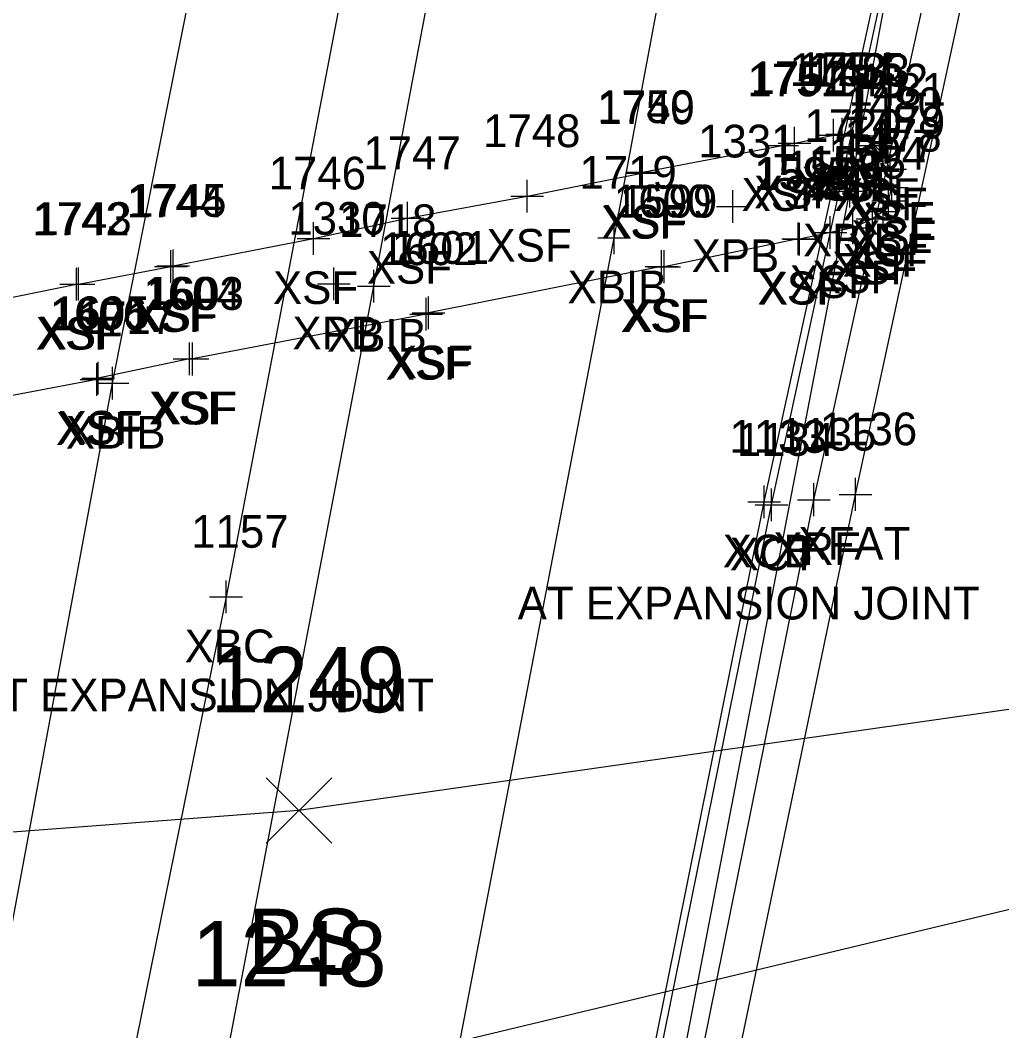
# Model space of a CAD drawing. Extents: x 1683147 to 1683637, y 416837 to 418211.
# Drawn here: x 1683250.16 to 1683280.15, y 417577.53 to 417608.4 of the extents above; entities that cross this region are included whole.
import ezdxf

# ---------------------------------------------------------------- set-up
doc = ezdxf.new("R2010")
doc.units = 0
for name, color, linetype in [('B_A', 7, 'Continuous'), ('B_C', 7, 'Continuous'), ('B_I', 7, 'Continuous'), ('B_TIC', 7, 'Continuous'), ('BB', 7, 'Continuous'), ('BDC', 7, 'Continuous'), ('BDEFAULT', 7, 'Continuous'), ('BELB', 7, 'Continuous'), ('BF', 7, 'Continuous'), ('BR', 7, 'Continuous'), ('L_A', 7, 'Continuous'), ('L_I', 7, 'Continuous'), ('L_TIC', 7, 'Continuous'), ('LELB', 7, 'Continuous')]:
    doc.layers.add(name, color=color, linetype=linetype)

msp = doc.modelspace()

# ---------------------------------------------------------------- linework, layer by layer
at = {"layer": 'B_TIC'}
for p, q in [((1683275.274, 417604.925), (1683275.35, 417604.925)), ((1683273.821, 417604.651), (1683273.897, 417604.651)), ((1683275.014, 417604.895), (1683275.09, 417604.895)), ((1683275.554, 417604.898), (1683275.63, 417604.898)), ((1683275.554, 417604.898), (1683275.63, 417604.898)), ((1683275.715, 417604.873), (1683275.79, 417604.873)), ((1683273.443, 417604.578), (1683273.518, 417604.578)), ((1683276.275, 417604.577), (1683276.35, 417604.577)), ((1683276.531, 417604.291), (1683276.606, 417604.291)), ((1683269.152, 417603.728), (1683269.227, 417603.728)), ((1683269.179, 417603.761), (1683269.255, 417603.761)), ((1683276.74, 417603.852), (1683276.816, 417603.852)), ((1683275.507, 417603.185), (1683275.583, 417603.185)), ((1683276.796, 417603.288), (1683276.871, 417603.288)), ((1683265.649, 417603.025), (1683265.725, 417603.025)), ((1683276.686, 417602.886), (1683276.761, 417602.886)), ((1683271.938, 417602.71), (1683272.014, 417602.71)), ((1683276.526, 417602.564), (1683276.602, 417602.564)), ((1683276.526, 417602.564), (1683276.602, 417602.564)), ((1683261.992, 417602.352), (1683262.067, 417602.352)), ((1683276.204, 417602.336), (1683276.28, 417602.336)), ((1683274.912, 417601.914), (1683274.988, 417601.914)), ((1683275.595, 417602.06), (1683275.671, 417602.06)), ((1683259.126, 417601.732), (1683259.201, 417601.732)), ((1683268.313, 417601.755), (1683268.388, 417601.755)), ((1683273.931, 417601.725), (1683274.007, 417601.725)), ((1683273.968, 417601.715), (1683274.043, 417601.715)), ((1683254.762, 417600.879), (1683254.838, 417600.879)), ((1683254.836, 417600.898), (1683254.912, 417600.898)), ((1683269.754, 417600.879), (1683269.829, 417600.879)), ((1683269.835, 417600.873), (1683269.91, 417600.873)), ((1683251.877, 417600.335), (1683251.953, 417600.335)), ((1683251.94, 417600.343), (1683252.015, 417600.343)), ((1683259.743, 417600.349), (1683259.819, 417600.349)), ((1683260.967, 417600.277), (1683261.042, 417600.277)), ((1683262.566, 417599.42), (1683262.641, 417599.42)), ((1683262.636, 417599.459), (1683262.712, 417599.459)), ((1683255.334, 417598.055), (1683255.41, 417598.055)), ((1683255.429, 417598.053), (1683255.505, 417598.053)), ((1683252.498, 417597.429), (1683252.574, 417597.429)), ((1683252.546, 417597.465), (1683252.621, 417597.465)), ((1683252.984, 417597.315), (1683253.06, 417597.315)), ((1683275.682, 417593.916), (1683275.758, 417593.916)), ((1683272.889, 417593.685), (1683272.965, 417593.685)), ((1683273.119, 417593.593), (1683273.195, 417593.593)), ((1683274.409, 417593.753), (1683274.485, 417593.753)), ((1683256.45, 417590.785), (1683256.526, 417590.785))]:
    msp.add_line(p, q, dxfattribs=at)
for points in [[(1683275.011, 417604.395), (1683275.011, 417605.395)], [(1683275.271, 417604.425), (1683275.271, 417605.425)], [(1683275.551, 417604.398), (1683275.551, 417605.398)], [(1683275.551, 417604.398), (1683275.551, 417605.398)], [(1683275.711, 417604.373), (1683275.711, 417605.373)], [(1683273.439, 417604.078), (1683273.439, 417605.078)], [(1683273.818, 417604.151), (1683273.818, 417605.151)], [(1683274.771, 417604.925), (1683275.771, 417604.925)], [(1683276.271, 417604.077), (1683276.271, 417605.077)], [(1683273.318, 417604.651), (1683274.318, 417604.651)], [(1683274.511, 417604.895), (1683275.511, 417604.895)], [(1683275.051, 417604.898), (1683276.051, 417604.898)], [(1683275.051, 417604.898), (1683276.051, 417604.898)], [(1683275.211, 417604.873), (1683276.211, 417604.873)], [(1683276.527, 417603.791), (1683276.527, 417604.791)], [(1683272.939, 417604.578), (1683273.939, 417604.578)], [(1683275.771, 417604.577), (1683276.771, 417604.577)], [(1683276.737, 417603.352), (1683276.737, 417604.352)], [(1683269.148, 417603.228), (1683269.148, 417604.228)], [(1683269.176, 417603.26), (1683269.176, 417604.261)], [(1683276.027, 417604.291), (1683277.027, 417604.291)], [(1683268.648, 417603.728), (1683269.648, 417603.728)], [(1683268.676, 417603.761), (1683269.676, 417603.761)], [(1683275.504, 417602.685), (1683275.504, 417603.685)], [(1683276.237, 417603.852), (1683277.237, 417603.852)], [(1683276.792, 417602.788), (1683276.792, 417603.788)], [(1683265.646, 417602.525), (1683265.646, 417603.525)], [(1683276.682, 417602.386), (1683276.682, 417603.386)], [(1683271.935, 417602.21), (1683271.935, 417603.21)], [(1683275.004, 417603.185), (1683276.004, 417603.185)], [(1683276.292, 417603.288), (1683277.292, 417603.288)], [(1683276.523, 417602.064), (1683276.523, 417603.064)], [(1683276.523, 417602.064), (1683276.523, 417603.064)], [(1683261.988, 417601.852), (1683261.988, 417602.852)], [(1683265.146, 417603.025), (1683266.146, 417603.025)], [(1683276.182, 417602.886), (1683277.182, 417602.886)], [(1683276.201, 417601.836), (1683276.201, 417602.836)], [(1683271.435, 417602.71), (1683272.435, 417602.71)], [(1683275.592, 417601.56), (1683275.592, 417602.56)], [(1683276.023, 417602.564), (1683277.023, 417602.564)], [(1683276.023, 417602.564), (1683277.023, 417602.564)], [(1683259.122, 417601.232), (1683259.122, 417602.232)], [(1683261.488, 417602.352), (1683262.488, 417602.352)], [(1683268.309, 417601.255), (1683268.309, 417602.255)], [(1683273.928, 417601.225), (1683273.928, 417602.225)], [(1683273.964, 417601.215), (1683273.964, 417602.215)], [(1683274.909, 417601.414), (1683274.909, 417602.414)], [(1683275.701, 417602.336), (1683276.701, 417602.336)], [(1683274.409, 417601.914), (1683275.409, 417601.914)], [(1683275.092, 417602.06), (1683276.092, 417602.06)], [(1683258.622, 417601.732), (1683259.622, 417601.732)], [(1683267.809, 417601.755), (1683268.809, 417601.755)], [(1683273.428, 417601.725), (1683274.428, 417601.725)], [(1683273.464, 417601.715), (1683274.464, 417601.715)], [(1683254.759, 417600.379), (1683254.759, 417601.379)], [(1683254.833, 417600.398), (1683254.833, 417601.398)], [(1683269.75, 417600.379), (1683269.75, 417601.379)], [(1683269.831, 417600.373), (1683269.831, 417601.373)], [(1683251.874, 417599.835), (1683251.874, 417600.835)], [(1683251.936, 417599.843), (1683251.936, 417600.843)], [(1683254.259, 417600.879), (1683255.259, 417600.879)], [(1683254.333, 417600.898), (1683255.333, 417600.898)], [(1683259.74, 417599.849), (1683259.74, 417600.849)], [(1683260.963, 417599.777), (1683260.963, 417600.777)], [(1683269.25, 417600.879), (1683270.25, 417600.879)], [(1683269.331, 417600.873), (1683270.331, 417600.873)], [(1683251.374, 417600.335), (1683252.374, 417600.335)], [(1683251.436, 417600.343), (1683252.436, 417600.343)], [(1683259.24, 417600.349), (1683260.24, 417600.349)], [(1683260.463, 417600.277), (1683261.463, 417600.277)], [(1683262.562, 417598.92), (1683262.562, 417599.92)], [(1683262.633, 417598.959), (1683262.633, 417599.959)], [(1683262.062, 417599.42), (1683263.062, 417599.42)], [(1683262.133, 417599.459), (1683263.133, 417599.459)], [(1683255.331, 417597.555), (1683255.331, 417598.555)], [(1683255.426, 417597.553), (1683255.426, 417598.553)], [(1683252.495, 417596.929), (1683252.495, 417597.929)], [(1683252.542, 417596.965), (1683252.542, 417597.965)], [(1683252.981, 417596.815), (1683252.981, 417597.815)], [(1683254.831, 417598.055), (1683255.831, 417598.055)], [(1683254.926, 417598.053), (1683255.926, 417598.053)], [(1683251.995, 417597.429), (1683252.995, 417597.429)], [(1683252.042, 417597.465), (1683253.042, 417597.465)], [(1683252.481, 417597.315), (1683253.481, 417597.315)], [(1683272.886, 417593.185), (1683272.886, 417594.185)], [(1683274.406, 417593.253), (1683274.406, 417594.253)], [(1683275.679, 417593.416), (1683275.679, 417594.416)], [(1683273.116, 417593.093), (1683273.116, 417594.093)], [(1683275.179, 417593.916), (1683276.179, 417593.916)], [(1683272.386, 417593.685), (1683273.386, 417593.685)], [(1683272.616, 417593.593), (1683273.616, 417593.593)], [(1683273.906, 417593.753), (1683274.906, 417593.753)], [(1683256.447, 417590.285), (1683256.447, 417591.285)], [(1683255.947, 417590.785), (1683256.947, 417590.785)]]:
    msp.add_lwpolyline(points, dxfattribs=at)
at = {"layer": 'BB'}
for points in [[(1683247.534, 417457.283), (1683256.806, 417505.82), (1683275.504, 417603.185), (1683284.507, 417651.57)], [(1683240.224, 417455.825), (1683249.612, 417504.3), (1683268.309, 417601.755), (1683277.362, 417650.167)], [(1683233.056, 417454.423), (1683242.375, 417502.873), (1683260.963, 417600.277), (1683270.09, 417648.672)], [(1683225.817, 417452.979), (1683235.185, 417501.44), (1683252.981, 417597.315), (1683262.91, 417647.271)]]:
    msp.add_lwpolyline(points, dxfattribs=at)
at = {"layer": 'BDC'}
for points in [[(1683248.206, 417455.394), (1683254.065, 417491.776), (1683257.952, 417514.755), (1683266.138, 417559.151), (1683273.116, 417593.593), (1683281.173, 417630.923), (1683286.527, 417654.075)], [(1683248.051, 417455.436), (1683253.896, 417491.851), (1683257.783, 417514.592), (1683265.936, 417559.114), (1683272.886, 417593.685), (1683281.07, 417631.095), (1683286.315, 417653.984)]]:
    msp.add_lwpolyline(points, dxfattribs=at)
at = {"layer": 'BDEFAULT'}
for points in [[(1683247.658, 417599.481), (1683251.874, 417600.335), (1683251.936, 417600.343), (1683254.759, 417600.879), (1683254.833, 417600.898), (1683259.122, 417601.732), (1683261.988, 417602.352), (1683265.646, 417603.025), (1683269.148, 417603.728), (1683269.176, 417603.761), (1683273.439, 417604.578), (1683273.818, 417604.651), (1683275.011, 417604.895), (1683275.271, 417604.925), (1683275.551, 417604.898)], [(1683276.523, 417602.564), (1683276.682, 417602.886), (1683276.792, 417603.288), (1683276.737, 417603.852), (1683276.527, 417604.291), (1683276.271, 417604.577), (1683275.711, 417604.873), (1683275.551, 417604.898)], [(1683276.523, 417602.564), (1683276.201, 417602.336), (1683275.592, 417602.06), (1683274.909, 417601.914), (1683273.964, 417601.715), (1683273.928, 417601.725), (1683269.831, 417600.873), (1683269.75, 417600.879), (1683262.633, 417599.459), (1683262.562, 417599.42), (1683255.426, 417598.053), (1683255.331, 417598.055), (1683252.542, 417597.465), (1683252.495, 417597.429), (1683248.196, 417596.611)]]:
    msp.add_lwpolyline(points, dxfattribs=at)
at = {"layer": 'BELB'}
msp.add_lwpolyline([(1683269.206, 417650.948), (1683260.393, 417611.397), (1683256.447, 417590.785), (1683246.822, 417543.339), (1683241.399, 417511.39), (1683234.932, 417474.067), (1683231.661, 417452.147)], dxfattribs=at)
at = {"layer": 'BF'}
msp.add_lwpolyline([(1683250.624, 417454.9), (1683256.47, 417491.459), (1683260.265, 417514.98), (1683268.347, 417558.692), (1683275.679, 417593.916), (1683283.544, 417630.285), (1683288.924, 417653.565)], dxfattribs=at)
at = {"layer": 'BR'}
msp.add_lwpolyline([(1683248.519, 417448.641), (1683249.479, 417455.186), (1683255.278, 417491.444), (1683259.237, 417514.807), (1683267.406, 417559.099), (1683274.406, 417593.753), (1683282.508, 417630.53), (1683290.526, 417665.488)], dxfattribs=at)
at = {"layer": 'L_TIC'}
for points in [[(1683257.675, 417583.256), (1683259.675, 417585.256)], [(1683259.675, 417583.256), (1683257.675, 417585.256)]]:
    msp.add_lwpolyline(points, dxfattribs=at)
at = {"layer": 'LELB'}
for points in [[(1683285.091, 417588.015), (1683258.675, 417584.256), (1683207.806, 417580.406)], [(1683286.499, 417582.7), (1683258.094, 417575.88), (1683207.744, 417572.779)]]:
    msp.add_lwpolyline(points, dxfattribs=at)

# ---------------------------------------------------------------- texts
at = {"layer": 'B_A'}
for s, p in [('XSF', (1683273.771, 417602.895)), ('XSF', (1683274.03, 417602.925)), ('XSF', (1683274.311, 417602.898)), ('XSF', (1683274.311, 417602.898)), ('XSF', (1683274.471, 417602.873)), ('XSF', (1683272.199, 417602.578)), ('XSF', (1683272.578, 417602.651)), ('XSF', (1683275.031, 417602.577)), ('XSF', (1683275.287, 417602.291)), ('XSF', (1683267.936, 417601.761)), ('XSF', (1683275.497, 417601.852)), ('XSF', (1683267.908, 417601.728)), ('XBIB', (1683274.075, 417601.185)), ('XSF', (1683275.552, 417601.288)), ('XSF', (1683264.406, 417601.025)), ('XSF', (1683275.442, 417600.886)), ('XPB', (1683270.671, 417600.71)), ('XSF', (1683275.282, 417600.564)), ('XSF', (1683275.282, 417600.564)), ('XSF', (1683260.748, 417600.352)), ('XSF', (1683274.961, 417600.336)), ('XSF', (1683273.669, 417599.914)), ('XSF', (1683274.351, 417600.06)), ('XSF', (1683257.882, 417599.732)), ('XBIB', (1683266.88, 417599.755)), ('XSF', (1683272.688, 417599.725)), ('XSF', (1683272.724, 417599.715)), ('XSF', (1683253.519, 417598.879)), ('XSF', (1683253.593, 417598.898)), ('XSF', (1683268.51, 417598.879)), ('XSF', (1683268.591, 417598.873)), ('XSF', (1683250.634, 417598.335)), ('XSF', (1683250.696, 417598.343)), ('XPB', (1683258.476, 417598.349)), ('XBIB', (1683259.534, 417598.277)), ('XSF', (1683261.322, 417597.42)), ('XSF', (1683261.393, 417597.459)), ('XSF', (1683254.091, 417596.055)), ('XSF', (1683254.186, 417596.053)), ('XSF', (1683251.254, 417595.429)), ('XSF', (1683251.302, 417595.465)), ('XBIB', (1683251.552, 417595.315)), ('XFAT', (1683273.934, 417591.916)), ('XCB', (1683271.622, 417591.685)), ('XCT', (1683271.836, 417591.593)), ('XRF', (1683273.166, 417591.753)), ('XBC', (1683255.183, 417588.785))]:
    msp.add_text(s, height=1, dxfattribs=at).set_placement(p)
at = {"layer": 'B_C'}
for p in [(1683265.356, 417590.093), (1683248.687, 417587.285)]:
    msp.add_text('AT EXPANSION JOINT', height=1, dxfattribs=at).set_placement(p)
at = {"layer": 'B_I'}
for s, p in [('1753', (1683273.664, 417606.395)), ('1754', (1683273.924, 417606.425)), ('1755', (1683274.204, 417606.398)), ('1755', (1683274.204, 417606.398)), ('1483', (1683274.365, 417606.373)), ('1751', (1683272.376, 417606.078)), ('1752', (1683272.471, 417606.151)), ('1482', (1683274.925, 417606.077)), ('1481', (1683275.465, 417605.791)), ('1750', (1683267.786, 417605.261)), ('1749', (1683267.798, 417605.228)), ('1480', (1683275.347, 417605.352)), ('1748', (1683264.3, 417604.525)), ('1720', (1683274.114, 417604.685)), ('1479', (1683275.442, 417604.788)), ('1331', (1683270.872, 417604.21)), ('1478', (1683275.336, 417604.386)), ('1477', (1683275.176, 417604.064)), ('1477', (1683275.176, 417604.064)), ('1747', (1683260.642, 417603.852)), ('1594', (1683274.855, 417603.836)), ('1596', (1683273.535, 417603.414)), ('1595', (1683274.245, 417603.56)), ('1746', (1683257.749, 417603.232)), ('1719', (1683267.242, 417603.255)), ('1598', (1683272.581, 417603.225)), ('1597', (1683272.618, 417603.215)), ('1744', (1683253.413, 417602.379)), ('1745', (1683253.486, 417602.398)), ('1600', (1683268.298, 417602.379)), ('1599', (1683268.481, 417602.373)), ('1742', (1683250.528, 417601.835)), ('1743', (1683250.59, 417601.843)), ('1330', (1683258.35, 417601.849)), ('1718', (1683259.9, 417601.777)), ('1602', (1683261.153, 417600.92)), ('1601', (1683261.507, 417600.959)), ('1604', (1683253.922, 417599.555)), ('1603', (1683254.017, 417599.553)), ('1605', (1683251.133, 417598.965)), ('1606', (1683251.058, 417598.929)), ('1717', (1683251.918, 417598.815)), ('1136', (1683274.588, 417595.416)), ('1133', (1683271.823, 417595.185)), ('1134', (1683272.053, 417595.093)), ('1135', (1683273.343, 417595.253)), ('1157', (1683255.384, 417592.285))]:
    msp.add_text(s, height=1, dxfattribs=at).set_placement(p)
at = {"layer": 'L_A'}
msp.add_text('BS', height=2, dxfattribs=at).set_placement((1683257.116, 417579.256))
at = {"layer": 'L_I'}
for s, p in [('1249', (1683255.975, 417587.256)), ('1248', (1683255.401, 417578.88))]:
    msp.add_text(s, height=2, dxfattribs=at).set_placement(p)

doc.saveas('drawing.dxf')
